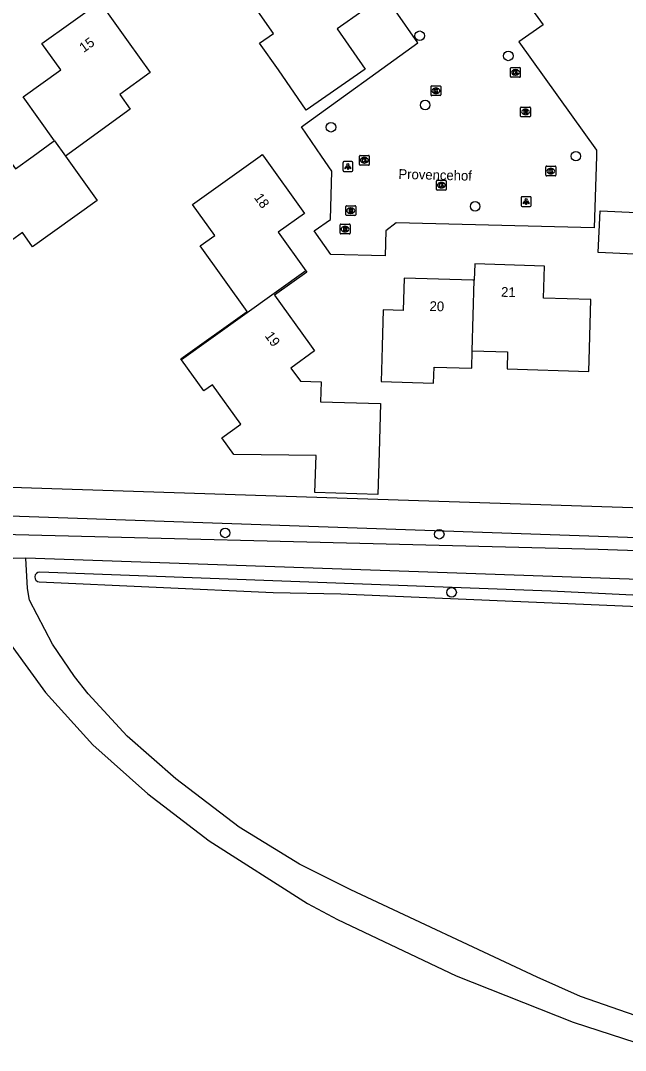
# Model space of a CAD drawing. Extents: x 158461 to 159795, y 387220 to 388672.
# Drawn here: x 159278.2 to 159340, y 387658.6 to 387763.8 of the extents above; entities that cross this region are included whole.
import ezdxf

# ---------------------------------------------------------------- set-up
doc = ezdxf.new("R2010")
doc.units = 0
for name, color, linetype in [('IMGEO_Boom', 7, 'Continuous'), ('IMGEO_Brandkraan', 7, 'Continuous'), ('IMGEO_Kolk', 7, 'Continuous'), ('IMGEO_Lichtpunt', 7, 'Continuous'), ('IMGEO_Openbare_ruimte_label', 7, 'Continuous'), ('IMGEO_Pand', 7, 'Continuous'), ('IMGEO_Pand_nummerreeks', 7, 'Continuous'), ('IMGEO_Rijbaan_lokaal_open', 7, 'Continuous'), ('IMGEO_Rioolput', 7, 'Continuous'), ('IMGEO_Voetpad_halfverhard', 7, 'Continuous'), ('IMGEO_Voetpad_onverhard', 7, 'Continuous'), ('IMGEO_Waterloop', 7, 'Continuous')]:
    doc.layers.add(name, color=color, linetype=linetype)

msp = doc.modelspace()

# ---------------------------------------------------------------- linework, layer by layer
at = {"layer": 'IMGEO_Boom'}
for centre in [(159318.96, 387762.3), (159328.02, 387760.24), (159319.52, 387755.22), (159309.89, 387752.95), (159334.93, 387749.99), (159324.63, 387744.86), (159299.07, 387711.48), (159320.96, 387711.34), (159322.22, 387705.4)]:
    msp.add_circle(centre, 0.489, dxfattribs=at)
at = {"layer": 'IMGEO_Brandkraan'}
for p, q in [((159311.42, 387744), (159311.42, 387744.85)), ((159311.49, 387744.92), (159312.34, 387744.92)), ((159311.9, 387744.7), (159311.93, 387744.7)), ((159312.42, 387744.85), (159312.42, 387744)), ((159312.34, 387743.92), (159311.49, 387743.92)), ((159311.93, 387744.14), (159311.9, 387744.14))]:
    msp.add_line(p, q, dxfattribs=at)
for points in [[(159311.42, 387744), (159311.42, 387744.85)], [(159311.49, 387744.92), (159312.34, 387744.92)], [(159311.76, 387744.62), (159311.76, 387744.22), (159311.98, 387744.22)], [(159312, 387744.62), (159311.76, 387744.62)], [(159311.94, 387744.54), (159311.89, 387744.54), (159311.89, 387744.47)], [(159311.89, 387744.47), (159311.94, 387744.47)], [(159311.95, 387744.39), (159311.89, 387744.39), (159311.89, 387744.31)], [(159311.89, 387744.31), (159311.95, 387744.31)], [(159312.42, 387744.85), (159312.42, 387744)], [(159312.34, 387743.92), (159311.49, 387743.92)]]:
    msp.add_lwpolyline(points, dxfattribs=at)
for centre, radius, start, end in [((159311.49, 387744.85), 0.0765, 91.552, 178.448), ((159311.49, 387744.85), 0.0765, 91.552, 178.448), ((159311.94, 387744.5), 0.0379, 267.8285, 90.9355), ((159311.95, 387744.35), 0.0404, 269.8759, 90.5077), ((159311.98, 387744.47), 0.251, 268.6676, 293.5347), ((159312, 387744.48), 0.145, 59.4692, 91.5367), ((159312.02, 387744.52), 0.0922, 285.5137, 58.1501), ((159312.03, 387744.33), 0.105, 301.3115, 78.989), ((159312.34, 387744.85), 0.0765, 1.552, 88.448), ((159312.34, 387744.85), 0.0765, 1.552, 88.448), ((159311.49, 387744), 0.0765, 181.552, 268.448), ((159311.49, 387744), 0.0765, 181.552, 268.448), ((159312.34, 387744), 0.0765, 271.552, 358.448), ((159312.34, 387744), 0.0765, 271.552, 358.448)]:
    msp.add_arc(centre, radius, start, end, dxfattribs=at)
for centre, major_axis, ratio, start_param, end_param in [((159311.9, 387744.42), (-0.387, 0.002), 0.722429, 4.712389, 7.853982), ((159311.93, 387744.42), (-0.39, 0.002), 0.717154, 1.570796, 4.712389)]:
    msp.add_ellipse(centre, major_axis=major_axis, ratio=ratio, start_param=start_param, end_param=end_param, dxfattribs=at)
at = {"layer": 'IMGEO_Kolk'}
for p, q in [((159328.25, 387758.13), (159328.25, 387758.98)), ((159328.33, 387759.06), (159329.18, 387759.06)), ((159329.25, 387758.98), (159329.25, 387758.13)), ((159329.18, 387758.06), (159328.33, 387758.06)), ((159328.74, 387758.84), (159328.76, 387758.84)), ((159328.76, 387758.28), (159328.74, 387758.28)), ((159320.12, 387756.25), (159320.12, 387757.1)), ((159320.19, 387757.18), (159321.04, 387757.18)), ((159320.6, 387756.96), (159320.63, 387756.96)), ((159321.12, 387757.1), (159321.12, 387756.25)), ((159321.04, 387756.18), (159320.19, 387756.18)), ((159320.63, 387756.4), (159320.6, 387756.4)), ((159312.81, 387749.14), (159312.81, 387749.99)), ((159312.88, 387750.07), (159313.73, 387750.07)), ((159313.29, 387749.85), (159313.32, 387749.85)), ((159313.81, 387749.99), (159313.81, 387749.14)), ((159313.73, 387749.07), (159312.88, 387749.07)), ((159313.32, 387749.29), (159313.29, 387749.29)), ((159331.87, 387748.04), (159331.87, 387748.9)), ((159331.95, 387748.97), (159332.8, 387748.97)), ((159332.36, 387748.75), (159332.39, 387748.75)), ((159332.87, 387748.9), (159332.87, 387748.04)), ((159320.68, 387746.6), (159320.68, 387747.45)), ((159320.75, 387747.53), (159321.61, 387747.53)), ((159321.17, 387747.31), (159321.19, 387747.31)), ((159321.68, 387747.45), (159321.68, 387746.6)), ((159332.8, 387747.97), (159331.95, 387747.97)), ((159332.38, 387748.19), (159332.36, 387748.19)), ((159321.61, 387746.53), (159320.75, 387746.53)), ((159321.19, 387746.75), (159321.16, 387746.75))]:
    msp.add_line(p, q, dxfattribs=at)
for points in [[(159328.25, 387758.13), (159328.25, 387758.98)], [(159328.33, 387759.06), (159329.18, 387759.06)], [(159329.25, 387758.98), (159329.25, 387758.13)], [(159329.18, 387758.06), (159328.33, 387758.06)], [(159328.57, 387758.76), (159328.7, 387758.76), (159328.7, 387758.61), (159328.82, 387758.76), (159328.99, 387758.76), (159328.84, 387758.61), (159329, 387758.36), (159328.84, 387758.36), (159328.76, 387758.52), (159328.7, 387758.46), (159328.7, 387758.36), (159328.57, 387758.36), (159328.57, 387758.76)], [(159320.12, 387756.25), (159320.12, 387757.1)], [(159320.19, 387757.18), (159321.04, 387757.18)], [(159320.44, 387756.88), (159320.56, 387756.88), (159320.56, 387756.72), (159320.69, 387756.88), (159320.85, 387756.88), (159320.71, 387756.73), (159320.86, 387756.48), (159320.71, 387756.48), (159320.62, 387756.64), (159320.56, 387756.57), (159320.56, 387756.48), (159320.44, 387756.48), (159320.44, 387756.88)], [(159321.12, 387757.1), (159321.12, 387756.25)], [(159321.04, 387756.18), (159320.19, 387756.18)], [(159312.81, 387749.14), (159312.81, 387749.99)], [(159312.88, 387750.07), (159313.73, 387750.07)], [(159313.13, 387749.77), (159313.25, 387749.77), (159313.25, 387749.62), (159313.38, 387749.77), (159313.54, 387749.77), (159313.4, 387749.62), (159313.55, 387749.37), (159313.4, 387749.37), (159313.31, 387749.53), (159313.25, 387749.46), (159313.25, 387749.37), (159313.13, 387749.37), (159313.13, 387749.77)], [(159313.81, 387749.99), (159313.81, 387749.14)], [(159313.73, 387749.07), (159312.88, 387749.07)], [(159331.87, 387748.04), (159331.87, 387748.9)], [(159331.95, 387748.97), (159332.8, 387748.97)], [(159332.19, 387748.67), (159332.32, 387748.67), (159332.32, 387748.52), (159332.45, 387748.67), (159332.61, 387748.67), (159332.47, 387748.52), (159332.62, 387748.27), (159332.47, 387748.27), (159332.38, 387748.44), (159332.32, 387748.37), (159332.32, 387748.27), (159332.19, 387748.27), (159332.19, 387748.67)], [(159332.87, 387748.9), (159332.87, 387748.04)], [(159320.68, 387746.6), (159320.68, 387747.45)], [(159320.75, 387747.53), (159321.61, 387747.53)], [(159321.68, 387747.45), (159321.68, 387746.6)], [(159332.8, 387747.97), (159331.95, 387747.97)], [(159321.61, 387746.53), (159320.75, 387746.53)], [(159321, 387747.23), (159321.12, 387747.23), (159321.12, 387747.08), (159321.25, 387747.23), (159321.42, 387747.23), (159321.27, 387747.08), (159321.42, 387746.83), (159321.27, 387746.83), (159321.19, 387746.99), (159321.12, 387746.93), (159321.12, 387746.83), (159321, 387746.83), (159321, 387747.23)]]:
    msp.add_lwpolyline(points, dxfattribs=at)
for centre, start, end in [((159328.33, 387758.98), 91.552, 178.448), ((159328.33, 387758.98), 91.552, 178.448), ((159329.18, 387758.98), 1.552, 88.448), ((159329.18, 387758.98), 1.552, 88.448), ((159328.33, 387758.13), 181.552, 268.448), ((159328.33, 387758.13), 181.552, 268.448), ((159329.18, 387758.13), 271.552, 358.448), ((159329.18, 387758.13), 271.552, 358.448), ((159320.19, 387757.1), 91.552, 178.448), ((159320.19, 387757.1), 91.552, 178.448), ((159321.04, 387757.1), 1.552, 88.448), ((159321.04, 387757.1), 1.552, 88.448), ((159320.19, 387756.25), 181.552, 268.448), ((159320.19, 387756.25), 181.552, 268.448), ((159321.04, 387756.25), 271.552, 358.448), ((159321.04, 387756.25), 271.552, 358.448), ((159312.88, 387749.99), 91.552, 178.448), ((159312.88, 387749.99), 91.552, 178.448), ((159313.73, 387749.99), 1.552, 88.448), ((159313.73, 387749.99), 1.552, 88.448), ((159312.88, 387749.14), 181.552, 268.448), ((159312.88, 387749.14), 181.552, 268.448), ((159313.73, 387749.14), 271.552, 358.448), ((159313.73, 387749.14), 271.552, 358.448), ((159331.95, 387748.9), 91.552, 178.448), ((159331.95, 387748.9), 91.552, 178.448), ((159332.8, 387748.9), 1.552, 88.448), ((159332.8, 387748.9), 1.552, 88.448), ((159320.75, 387747.45), 91.552, 178.448), ((159320.75, 387747.45), 91.552, 178.448), ((159321.6, 387747.45), 1.552, 88.448), ((159321.6, 387747.45), 1.552, 88.448), ((159331.95, 387748.05), 181.552, 268.448), ((159331.95, 387748.05), 181.552, 268.448), ((159332.8, 387748.05), 271.552, 358.448), ((159332.8, 387748.05), 271.552, 358.448), ((159320.75, 387746.6), 181.552, 268.448), ((159320.75, 387746.6), 181.552, 268.448), ((159321.6, 387746.6), 271.552, 358.448), ((159321.6, 387746.6), 271.552, 358.448)]:
    msp.add_arc(centre, 0.0765, start, end, dxfattribs=at)
for centre, major_axis, ratio, start_param, end_param in [((159328.74, 387758.56), (-0.387, 0.002), 0.722429, 4.712389, 7.853982), ((159328.76, 387758.56), (-0.39, 0.002), 0.717154, 1.570796, 4.712389), ((159320.6, 387756.68), (-0.387, 0.002), 0.722429, 4.712389, 7.853982), ((159320.63, 387756.68), (-0.39, 0.002), 0.717154, 1.570796, 4.712389), ((159313.29, 387749.57), (-0.387, 0.002), 0.722429, 4.712389, 7.853982), ((159313.32, 387749.57), (-0.39, 0.002), 0.717154, 1.570796, 4.712389), ((159332.36, 387748.47), (-0.387, 0.002), 0.722429, 4.712389, 7.853982), ((159332.38, 387748.47), (-0.39, 0.002), 0.717154, 1.570796, 4.712389), ((159321.17, 387747.03), (-0.387, 0.002), 0.722429, 4.712389, 7.853982), ((159321.19, 387747.03), (-0.39, 0.002), 0.717154, 1.570796, 4.712389)]:
    msp.add_ellipse(centre, major_axis=major_axis, ratio=ratio, start_param=start_param, end_param=end_param, dxfattribs=at)
at = {"layer": 'IMGEO_Lichtpunt'}
for p, q in [((159312.03, 387749.43), (159311.22, 387749.43)), ((159312.03, 387749.43), (159311.22, 387749.43)), ((159311.12, 387749.33), (159311.12, 387748.53)), ((159311.12, 387749.33), (159311.12, 387748.53)), ((159311.22, 387748.43), (159312.03, 387748.43)), ((159311.22, 387748.43), (159312.03, 387748.43)), ((159312.12, 387748.53), (159312.12, 387749.33)), ((159312.12, 387748.53), (159312.12, 387749.33)), ((159329.35, 387745.75), (159329.35, 387744.94)), ((159329.35, 387745.75), (159329.35, 387744.94)), ((159330.25, 387745.84), (159329.44, 387745.84)), ((159330.25, 387745.84), (159329.44, 387745.84)), ((159330.35, 387744.94), (159330.35, 387745.75)), ((159330.35, 387744.94), (159330.35, 387745.75)), ((159329.44, 387744.85), (159330.25, 387744.85)), ((159329.44, 387744.85), (159330.25, 387744.85))]:
    msp.add_line(p, q, dxfattribs=at)
for points in [[(159311.5, 387749), (159311.54, 387748.97), (159311.35, 387748.71), (159311.31, 387748.73), (159311.5, 387749)], [(159311.6, 387748.95), (159311.65, 387748.95), (159311.65, 387748.63), (159311.6, 387748.63), (159311.6, 387748.95)], [(159311.71, 387748.97), (159311.75, 387749), (159311.93, 387748.73), (159311.9, 387748.71), (159311.71, 387748.97)], [(159329.72, 387745.41), (159329.76, 387745.39), (159329.57, 387745.12), (159329.54, 387745.15), (159329.72, 387745.41)], [(159329.82, 387745.37), (159329.87, 387745.37), (159329.87, 387745.04), (159329.82, 387745.04), (159329.82, 387745.37)], [(159329.93, 387745.39), (159329.97, 387745.41), (159330.16, 387745.15), (159330.12, 387745.12), (159329.93, 387745.39)]]:
    msp.add_lwpolyline(points, dxfattribs=at)
for centre in [(159311.62, 387749.13), (159329.85, 387745.55)]:
    msp.add_circle(centre, 0.0994, dxfattribs=at)
for centre, start, end in [((159311.22, 387749.33), 90, 180), ((159311.22, 387749.33), 90, 180), ((159312.03, 387749.33), 0, 90), ((159312.03, 387749.33), 0, 90), ((159311.22, 387748.53), 180, 270), ((159311.22, 387748.53), 180, 270), ((159312.03, 387748.53), 270, 0), ((159312.03, 387748.53), 270, 360), ((159329.44, 387745.75), 90, 180), ((159329.44, 387745.75), 90, 180), ((159330.25, 387745.75), 0, 90), ((159330.25, 387745.75), 0, 90), ((159329.44, 387744.94), 180, 270), ((159329.44, 387744.94), 180, 270), ((159330.25, 387744.94), 270, 0), ((159330.25, 387744.94), 270, 360)]:
    msp.add_arc(centre, 0.0946, start, end, dxfattribs=at)
at = {"layer": 'IMGEO_Pand'}
for points in [[(159307.72, 387769.75), (159309.07, 387770.69), (159313.15, 387764.84), (159310.53, 387763.01), (159313.39, 387758.89), (159307.37, 387754.7), (159304.51, 387758.8), (159302.59, 387761.55), (159304, 387762.53), (159301.95, 387765.48), (159301.83, 387765.65)], [(159281.62, 387751.56), (159278.42, 387756.04), (159282.28, 387758.8), (159280.34, 387761.51), (159286.26, 387765.75), (159289.17, 387761.69), (159291.42, 387758.54), (159288.3, 387756.3), (159289.37, 387754.8), (159282.74, 387750)], [(159271.08, 387745.76), (159269.98, 387747.3), (159273.75, 387750), (159275.7, 387751.4), (159276.7, 387750), (159277.63, 387748.7), (159279.44, 387750), (159281.5, 387751.48), (159281.62, 387751.56)], [(159281.62, 387751.56), (159282.74, 387750)], [(159282.74, 387750), (159285.99, 387745.46), (159279.38, 387740.73), (159278.34, 387742.18), (159275.7, 387740.28), (159275.4, 387740.07), (159275.24, 387739.95)], [(159294.62, 387729.17), (159294.55, 387729.27), (159301.32, 387734.12), (159296.53, 387740.81), (159298.02, 387741.88), (159295.74, 387745.06), (159298.58, 387747.09), (159302.64, 387750), (159302.86, 387750.16), (159302.98, 387750), (159307.17, 387744.14), (159304.49, 387742.22), (159307.33, 387738.26)], [(159337.41, 387744.41), (159341.14, 387744.22), (159340.93, 387739.97), (159337.2, 387740.16), (159337.41, 387744.41)], [(159324.33, 387730.1), (159327.95, 387729.99), (159327.9, 387728.24), (159336.25, 387727.99), (159336.32, 387730.33), (159336.47, 387735.33), (159331.62, 387735.47), (159331.72, 387738.76), (159324.59, 387738.98), (159324.54, 387737.31)], [(159307.33, 387738.26), (159307.41, 387738.14), (159304.13, 387735.79), (159307.71, 387730.79), (159308.22, 387730.08), (159305.79, 387728.33), (159306.76, 387726.98), (159308.88, 387726.92), (159308.81, 387724.87), (159314.96, 387724.69), (159314.81, 387719.69), (159314.68, 387715.41), (159308.25, 387715.61), (159308.36, 387719.38), (159299.96, 387719.5), (159298.74, 387721.19), (159300.68, 387722.58), (159297.79, 387726.63), (159296.9, 387726), (159294.62, 387729.17)], [(159307.33, 387738.26), (159294.62, 387729.17)], [(159324.54, 387737.31), (159324.39, 387737.32), (159317.37, 387737.53), (159317.27, 387734.21), (159315.24, 387734.27), (159315.14, 387730.57), (159315.1, 387729.27), (159315.03, 387726.96), (159320.39, 387726.8), (159320.44, 387728.43), (159324.28, 387728.31), (159324.33, 387730.1)], [(159324.33, 387730.1), (159324.54, 387737.31)]]:
    msp.add_lwpolyline(points, dxfattribs=at)
at = {"layer": 'IMGEO_Rijbaan_lokaal_open'}
msp.add_lwpolyline([(159327.19, 387769.48), (159331.58, 387763.43), (159329.11, 387761.67), (159337.05, 387750.59), (159337.03, 387750), (159336.79, 387742.67), (159316.54, 387743.17), (159315.49, 387742.35), (159315.44, 387739.8), (159309.86, 387739.94), (159308.17, 387742.36), (159309.85, 387743.52), (159309.98, 387748.47), (159308.93, 387750), (159306.86, 387753), (159318.78, 387761.57), (159316.5, 387764.84)], dxfattribs=at)
at = {"layer": 'IMGEO_Rioolput'}
for p, q in [((159329.28, 387754.09), (159329.28, 387754.94)), ((159329.35, 387755.01), (159330.21, 387755.01)), ((159329.77, 387754.79), (159329.79, 387754.79)), ((159330.28, 387754.94), (159330.28, 387754.09)), ((159330.21, 387754.01), (159329.35, 387754.01)), ((159329.79, 387754.23), (159329.76, 387754.23)), ((159310.84, 387742.11), (159310.84, 387742.97)), ((159310.91, 387743.04), (159311.76, 387743.04)), ((159311.76, 387742.04), (159310.91, 387742.04)), ((159311.35, 387742.26), (159311.32, 387742.26)), ((159311.33, 387742.82), (159311.35, 387742.82)), ((159311.84, 387742.97), (159311.84, 387742.11))]:
    msp.add_line(p, q, dxfattribs=at)
for points in [[(159329.28, 387754.09), (159329.28, 387754.94)], [(159329.35, 387755.01), (159330.21, 387755.01)], [(159329.87, 387754.71), (159329.61, 387754.71), (159329.61, 387754.31)], [(159330.28, 387754.94), (159330.28, 387754.09)], [(159330.21, 387754.01), (159329.35, 387754.01)], [(159329.61, 387754.31), (159329.74, 387754.31), (159329.74, 387754.47), (159329.75, 387754.47)], [(159329.79, 387754.63), (159329.74, 387754.63), (159329.74, 387754.55)], [(159329.74, 387754.55), (159329.79, 387754.55)], [(159329.8, 387754.44), (159329.87, 387754.31), (159330.01, 387754.31), (159329.94, 387754.44)], [(159310.84, 387742.11), (159310.84, 387742.97)], [(159310.91, 387743.04), (159311.76, 387743.04)], [(159311.76, 387742.04), (159310.91, 387742.04)], [(159311.43, 387742.74), (159311.17, 387742.74), (159311.17, 387742.34)], [(159311.17, 387742.34), (159311.3, 387742.34), (159311.3, 387742.5), (159311.31, 387742.5)], [(159311.35, 387742.66), (159311.3, 387742.66), (159311.3, 387742.58)], [(159311.3, 387742.58), (159311.35, 387742.58)], [(159311.36, 387742.47), (159311.43, 387742.34), (159311.57, 387742.34), (159311.5, 387742.47)], [(159311.84, 387742.97), (159311.84, 387742.11)]]:
    msp.add_lwpolyline(points, dxfattribs=at)
for centre, radius, start, end in [((159329.35, 387754.94), 0.0765, 91.552, 178.448), ((159329.35, 387754.94), 0.0765, 91.552, 178.448), ((159329.87, 387754.6), 0.109, 350.3612, 89.416), ((159330.2, 387754.94), 0.0765, 1.552, 88.448), ((159330.2, 387754.94), 0.0765, 1.552, 88.448), ((159329.35, 387754.09), 0.0765, 181.552, 268.448), ((159329.35, 387754.09), 0.0765, 181.552, 268.448), ((159329.75, 387754.42), 0.0533, 26.0293, 88.6989), ((159329.8, 387754.53), 0.0964, 77.0061, 93.1865), ((159329.78, 387754.74), 0.19, 274.7715, 282.9687), ((159329.81, 387754.59), 0.0378, 276.6634, 79.6772), ((159329.86, 387754.6), 0.112, 277.5842, 350.9817), ((159329.85, 387754.38), 0.108, 29.5134, 73.7905), ((159330.2, 387754.09), 0.0765, 271.552, 358.448), ((159330.2, 387754.09), 0.0765, 271.552, 358.448), ((159310.91, 387742.97), 0.0765, 91.552, 178.448), ((159310.91, 387742.97), 0.0765, 91.552, 178.448), ((159310.91, 387742.12), 0.0765, 181.552, 268.448), ((159310.91, 387742.12), 0.0765, 181.552, 268.448), ((159311.31, 387742.45), 0.0533, 26.0293, 88.6989), ((159311.36, 387742.56), 0.0964, 77.0061, 93.1865), ((159311.33, 387742.77), 0.19, 274.7715, 282.9687), ((159311.37, 387742.62), 0.0378, 276.6634, 79.6772), ((159311.43, 387742.63), 0.109, 350.3612, 89.416), ((159311.42, 387742.63), 0.112, 277.5842, 350.9817), ((159311.41, 387742.41), 0.108, 29.5134, 73.7905), ((159311.76, 387742.97), 0.0765, 1.552, 88.448), ((159311.76, 387742.97), 0.0765, 1.552, 88.448), ((159311.76, 387742.12), 0.0765, 271.552, 358.448), ((159311.76, 387742.12), 0.0765, 271.552, 358.448)]:
    msp.add_arc(centre, radius, start, end, dxfattribs=at)
for centre, major_axis, ratio, start_param, end_param in [((159329.77, 387754.51), (-0.387, 0.002), 0.722429, 4.712389, 7.853982), ((159329.79, 387754.51), (-0.39, 0.002), 0.717154, 1.570796, 4.712389), ((159311.32, 387742.54), (-0.387, 0.002), 0.722429, 4.712389, 7.853982), ((159311.35, 387742.54), (-0.39, 0.002), 0.717154, 1.570796, 4.712389)]:
    msp.add_ellipse(centre, major_axis=major_axis, ratio=ratio, start_param=start_param, end_param=end_param, dxfattribs=at)
at = {"layer": 'IMGEO_Voetpad_halfverhard'}
for points in [[(159371.02, 387709.34), (159371.1, 387708.63), (159337.22, 387709.78), (159261.35, 387711.69), (159237.16, 387712.54), (159237.19, 387713.14)], [(159278.69, 387708.88), (159272.12, 387708.72)], [(159527.03, 387700.22), (159500, 387701.43), (159473.06, 387702.09), (159449.13, 387703.36), (159367.77, 387705.78), (159278.69, 387708.88)]]:
    msp.add_lwpolyline(points, dxfattribs=at)
at = {"layer": 'IMGEO_Voetpad_onverhard'}
for points in [[(159272.12, 387708.72), (159273.21, 387708.1), (159275.75, 387702.41), (159277.37, 387699.75), (159280.71, 387695.16), (159285.53, 387689.83), (159291.16, 387684.8), (159297.45, 387680.01), (159307.49, 387673.58), (159310.57, 387671.95), (159322.69, 387666.2), (159334.64, 387661.46), (159343.6, 387658.58)], [(159345, 387660.76), (159335.4, 387664.08), (159330.97, 387666.07), (159311.92, 387674.99), (159306.66, 387677.62), (159300.52, 387681.4), (159294.04, 387686.34), (159289.04, 387690.7), (159285.08, 387695.03), (159283.66, 387696.81), (159281.43, 387700.11), (159279.07, 387704.6), (159278.87, 387705.81), (159278.69, 387708.88)]]:
    msp.add_lwpolyline(points, dxfattribs=at)
at = {"layer": 'IMGEO_Waterloop'}
for points in [[(159239.68, 387717.37), (159366.76, 387713.24)], [(159239.52, 387714.51), (159368.81, 387710.04)], [(159523.96, 387699.43), (159500, 387700.26), (159471.26, 387701.05), (159434.66, 387701.64), (159404.5, 387702.89), (159358.22, 387704.27), (159332.37, 387705.52), (159280.11, 387707.46)], [(159280.05, 387706.47), (159303.98, 387705.4), (159310.9, 387705.24), (159356.49, 387703.32), (159396.68, 387701.8), (159441.57, 387700.67), (159491.75, 387698.33)]]:
    msp.add_lwpolyline(points, dxfattribs=at)
msp.add_arc((159280.1, 387706.96), 0.496, 88.1744, 264.7738, dxfattribs=at)

# ---------------------------------------------------------------- texts
at = {"layer": 'IMGEO_Openbare_ruimte_label'}
msp.add_text('Provencehof', height=1, rotation=358.5679, dxfattribs=at).set_placement((159316.78, 387747.67))
at = {"layer": 'IMGEO_Pand_nummerreeks'}
for s, rotation, p in [('15', 35.6151, (159284.61, 387760.54)), ('18', 305.6107, (159301.98, 387745.76)), ('21', 358.2926, (159327.27, 387735.62)), ('20', 358.2926, (159319.96, 387734.17)), ('19', 305.6126, (159303.08, 387731.62))]:
    msp.add_text(s, height=1, rotation=rotation, dxfattribs=at).set_placement(p)

doc.saveas('drawing.dxf')
